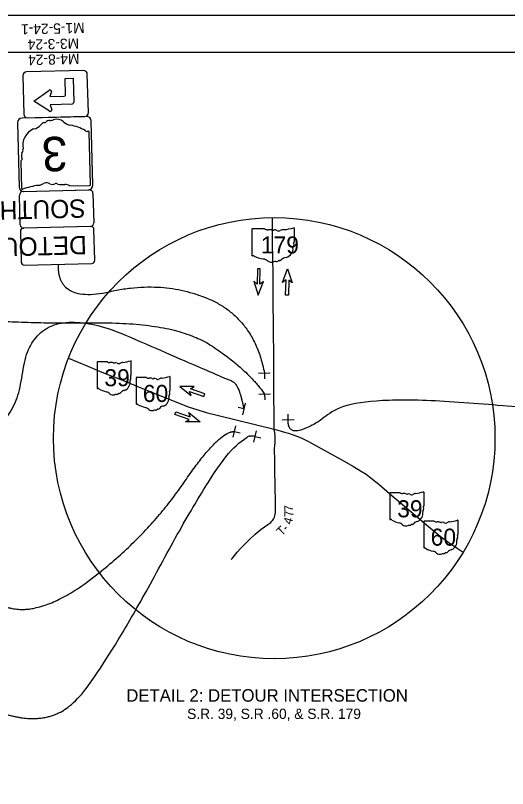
# Model space of a CAD drawing. Extents: x -15.3 to 34, y 0 to 22.
# Drawn here: x 20.86 to 27.55, y 11.48 to 22 of the extents above; entities that cross this region are included whole.
import ezdxf

# ---------------------------------------------------------------- set-up
doc = ezdxf.new("R2010")
doc.units = 0
for name, color, linetype in [('GM_X_State_Route', 7, 'Continuous'), ('GM_X_State_Shield', 7, 'Continuous'), ('GM_X_Township_Road', 7, 'Continuous'), ('GM_X_Township_Road_Text', 7, 'Continuous'), ('PM_P_Cells', 7, 'Continuous'), ('SC_Scratch1', 7, 'Continuous'), ('SH_Border', 7, 'Continuous'), ('SH_Cut_Line', 7, 'Continuous'), ('SH_Text', 7, 'Continuous'), ('SN_P_Signs', 7, 'Continuous')]:
    doc.layers.add(name, color=color, linetype=linetype)

msp = doc.modelspace()

# ---------------------------------------------------------------- linework, layer by layer
at = {"layer": 'GM_X_State_Route'}
for points in [[(21.578, 17.336), (21.841, 17.229), (22.002, 17.163), (22.124, 17.113), (22.266, 17.055), (22.388, 17.007), (22.509, 16.958), (22.651, 16.9), (23.116, 16.711), (23.218, 16.673), (23.322, 16.638), (23.448, 16.601), (23.617, 16.558), (24.374, 16.374), (24.372, 16.621), (24.368, 16.774), (24.369, 16.905), (24.369, 17.058), (24.368, 17.211), (24.369, 17.386), (24.365, 17.692), (24.364, 17.844), (24.362, 18.041), (24.36, 18.326), (24.359, 18.457), (24.356, 18.719), (24.353, 18.871), (24.351, 19.046), (24.351, 19.199), (24.351, 19.25)], [(24.374, 16.374), (24.409, 16.363), (24.47, 16.346), (24.515, 16.333), (24.567, 16.318), (24.62, 16.3), (24.682, 16.278), (24.743, 16.252), (24.841, 16.203), (25.015, 16.11), (25.283, 15.961), (25.454, 15.863), (25.549, 15.807), (25.623, 15.759), (25.693, 15.707), (25.795, 15.623), (25.978, 15.467), (26.145, 15.325), (26.445, 15.07), (26.632, 14.918), (26.736, 14.839), (26.861, 14.751), (26.942, 14.697)]]:
    msp.add_lwpolyline(points, dxfattribs=at)
at = {"layer": 'GM_X_State_Shield'}
for p, q in [((24.069, 19.09), (24.069, 18.737)), ((24.245, 19.096), (24.075, 19.096)), ((24.649, 18.92), (24.649, 19.104)), ((24.649, 18.92), (24.649, 18.92)), ((21.968, 17.283), (21.968, 16.931)), ((22.108, 17.289), (21.972, 17.289)), ((22.432, 17.114), (22.432, 17.298)), ((22.432, 17.114), (22.432, 17.114)), ((22.497, 17.07), (22.497, 16.717)), ((22.637, 17.076), (22.501, 17.076)), ((22.961, 16.9), (22.961, 17.084)), ((22.961, 16.9), (22.961, 16.9)), ((25.947, 15.5), (25.947, 15.148)), ((26.087, 15.506), (25.951, 15.506)), ((26.411, 15.331), (26.411, 15.515)), ((26.411, 15.331), (26.411, 15.331)), ((26.409, 15.114), (26.409, 14.762)), ((26.549, 15.12), (26.413, 15.12)), ((26.873, 14.945), (26.873, 15.129)), ((26.873, 14.945), (26.873, 14.945))]:
    msp.add_line(p, q, dxfattribs=at)
for centre, radius, start, end in [((21.973, 17.284), 0.00538, 98.1301, 188.1301), ((22.141, 17.33), 0.0521, 231.6195, 271.1119), ((22.158, 17.092), 0.187, 80.4867, 94.9883), ((22.2, 17.286), 0.015, 219.7921, 297.1024), ((22.222, 17.245), 0.0313, 54.4667, 119.1411), ((22.263, 17.301), 0.0376, 233.8562, 294.8282), ((22.329, 17.182), 0.099, 97.3462, 120.7689), ((22.267, 17.769), 0.492, 275.8445, 288.9065), ((22.427, 17.299), 0.00517, 351.8621, 97.738), ((22.45, 17.037), 0.0349, 136.8065, 186.9296), ((22.431, 17.1), 0.00799, 107.944, 210.337), ((22.38, 17.077), 0.048, 340.033, 23.6496), ((22.426, 17.113), 0.00553, 289.6038, 7.7341), ((22.502, 17.07), 0.00538, 98.1301, 188.1301), ((22.669, 17.117), 0.0521, 231.6195, 271.1119), ((22.687, 16.878), 0.187, 80.4867, 94.9883), ((22.729, 17.072), 0.015, 219.7921, 297.1024), ((22.751, 17.032), 0.0313, 54.4667, 119.1411), ((22.792, 17.087), 0.0376, 233.8562, 294.8282), ((22.858, 16.968), 0.099, 97.3462, 120.7689), ((22.795, 17.556), 0.492, 275.8445, 288.9065), ((22.955, 17.085), 0.00517, 351.8621, 97.738), ((22.294, 17.013), 0.123, 292.3089, 8.9858), ((21.973, 16.93), 0.00542, 171.9584, 258.3066), ((21.974, 16.966), 0.0414, 267.339, 280.6039), ((21.982, 16.911), 0.0149, 29.7484, 93.2717), ((22.171, 17.227), 0.355, 240.4129, 257.1985), ((22.065, 16.773), 0.111, 47.1842, 75.836), ((22.185, 16.909), 0.0706, 230.7004, 286.2918), ((22.226, 16.787), 0.058, 85.6951, 111.2099), ((22.231, 16.883), 0.0376, 268.777, 315.5493), ((22.265, 16.848), 0.0106, 65.7517, 132.6484), ((22.261, 16.897), 0.0398, 282.8732, 323.2771), ((22.346, 16.832), 0.0674, 94.4031, 142.5768), ((22.979, 16.823), 0.0349, 136.8065, 186.9296), ((22.959, 16.887), 0.00799, 107.944, 210.337), ((22.909, 16.863), 0.048, 340.033, 23.6496), ((22.955, 16.899), 0.00553, 289.6038, 7.7341), ((22.823, 16.8), 0.123, 292.3089, 8.9858), ((22.502, 16.717), 0.00542, 171.9584, 258.3066), ((22.503, 16.753), 0.0414, 267.339, 280.6039), ((22.511, 16.697), 0.0149, 29.7484, 93.2717), ((22.7, 17.014), 0.355, 240.4129, 257.1985), ((22.594, 16.559), 0.111, 47.1842, 75.836), ((22.714, 16.695), 0.0706, 230.7004, 286.2918), ((22.755, 16.574), 0.058, 85.6951, 111.2099), ((22.76, 16.669), 0.0376, 268.777, 315.5493), ((22.794, 16.635), 0.0106, 65.7517, 132.6484), ((22.789, 16.683), 0.0398, 282.8732, 323.2771), ((22.875, 16.619), 0.0674, 94.4031, 142.5768), ((25.952, 15.501), 0.00538, 98.1301, 188.1301), ((26.119, 15.547), 0.0521, 231.6195, 271.1119), ((26.137, 15.309), 0.187, 80.4867, 94.9883), ((26.179, 15.503), 0.015, 219.7921, 297.1024), ((26.201, 15.462), 0.0313, 54.4667, 119.1411), ((26.242, 15.518), 0.0376, 233.8562, 294.8282), ((26.308, 15.399), 0.099, 97.3462, 120.7689), ((26.245, 15.987), 0.492, 275.8445, 288.9065), ((26.405, 15.516), 0.00517, 351.8621, 97.738), ((26.273, 15.23), 0.123, 292.3089, 8.9858), ((26.429, 15.254), 0.0349, 136.8065, 186.9296), ((26.409, 15.317), 0.00799, 107.944, 210.337), ((26.359, 15.294), 0.048, 340.033, 23.6496), ((26.405, 15.33), 0.00553, 289.6038, 7.7341), ((25.952, 15.147), 0.00542, 171.9584, 258.3066), ((25.953, 15.183), 0.0414, 267.339, 280.6039), ((25.961, 15.128), 0.0149, 29.7484, 93.2717), ((26.15, 15.444), 0.355, 240.4129, 257.1985), ((26.044, 14.99), 0.111, 47.1842, 75.836), ((26.164, 15.126), 0.0706, 230.7004, 286.2918), ((26.205, 15.004), 0.058, 85.6951, 111.2099), ((26.21, 15.1), 0.0376, 268.777, 315.5493), ((26.244, 15.066), 0.0106, 65.7517, 132.6484), ((26.239, 15.114), 0.0398, 282.8732, 323.2771), ((26.325, 15.049), 0.0674, 94.4031, 142.5768), ((26.414, 15.115), 0.00538, 98.1301, 188.1301), ((26.582, 15.161), 0.0521, 231.6195, 271.1119), ((26.599, 14.923), 0.187, 80.4867, 94.9883), ((26.641, 15.117), 0.015, 219.7921, 297.1024), ((26.664, 15.076), 0.0313, 54.4667, 119.1411), ((26.704, 15.132), 0.0376, 233.8562, 294.8282), ((26.77, 15.013), 0.099, 97.3462, 120.7689), ((26.708, 15.601), 0.492, 275.8445, 288.9065), ((26.868, 15.13), 0.00517, 351.8621, 97.738), ((26.872, 14.931), 0.00799, 107.944, 210.337), ((26.867, 14.944), 0.00553, 289.6038, 7.7341), ((26.735, 14.844), 0.123, 292.3089, 8.9858), ((26.891, 14.868), 0.0349, 136.8065, 186.9296), ((26.821, 14.908), 0.048, 340.033, 23.6496), ((26.414, 14.761), 0.00542, 171.9584, 258.3066), ((26.415, 14.797), 0.0414, 267.339, 280.6039), ((26.423, 14.742), 0.0149, 29.7484, 93.2717), ((26.612, 15.058), 0.355, 240.4129, 257.1985), ((26.787, 14.663), 0.0674, 94.4031, 142.5768), ((26.506, 14.604), 0.111, 47.1842, 75.836), ((26.626, 14.74), 0.0706, 230.7004, 286.2918), ((26.667, 14.618), 0.058, 85.6951, 111.2099), ((26.672, 14.714), 0.0376, 268.777, 315.5493), ((26.706, 14.68), 0.0106, 65.7517, 132.6484), ((26.702, 14.728), 0.0398, 282.8732, 323.2771)]:
    msp.add_arc(centre, radius, start, end, dxfattribs=at)
for centre, major_axis, start_param, end_param in [((24.076, 19.09), (0.00672, 0), 1.712693, 3.28349), ((24.285, 19.137), (0.0652, 0), 4.042523, 4.731795), ((24.307, 18.898), (0.234, 0), 1.404758, 1.657858), ((24.36, 19.092), (0.0188, 0), 3.836095, 5.185415), ((24.388, 19.051), (0.0391, 0), 0.950623, 2.079405), ((24.438, 19.107), (0.047, 0), 4.081561, 5.145723), ((24.521, 18.988), (0.124, 0), 1.699011, 2.107814), ((24.443, 19.576), (0.615, 0), 4.814394, 5.042369), ((24.643, 19.105), (0.00646, 0), 6.141152, 7.989035), ((24.477, 18.82), (0.154, 0), 5.101752, 6.440018), ((24.672, 18.843), (0.0436, 0), 2.387724, 3.262537), ((24.648, 18.907), (0.00999, 0), 1.883978, 3.671073), ((24.584, 18.883), (0.06, 0), 5.934695, 6.695948), ((24.642, 18.919), (0.00691, 0), 5.05454, 6.418171), ((24.076, 18.737), (0.00678, 0), 3.00124, 4.508301), ((24.077, 18.773), (0.0517, 0), 4.665946, 4.897461), ((24.088, 18.717), (0.0187, 0), 0.519207, 1.627899), ((24.323, 19.034), (0.444, 0), 4.195997, 4.488961), ((24.191, 18.579), (0.139, 0), 0.823519, 1.323587), ((24.341, 18.715), (0.0882, 0), 4.026481, 4.996735), ((24.392, 18.594), (0.0725, 0), 1.495662, 1.94098), ((24.398, 18.689), (0.047, 0), 4.691044, 5.507374), ((24.441, 18.655), (0.0132, 0), 1.147584, 2.315152), ((24.435, 18.703), (0.0497, 0), 4.937069, 5.64225), ((24.542, 18.639), (0.0843, 0), 1.647645, 2.488434)]:
    msp.add_ellipse(centre, major_axis=major_axis, ratio=0.8, start_param=start_param, end_param=end_param, dxfattribs=at)
at = {"layer": 'GM_X_Township_Road'}
msp.add_lwpolyline([(23.79, 14.598), (23.805, 14.614), (23.872, 14.699), (23.915, 14.748), (23.96, 14.796), (24.039, 14.871), (24.116, 14.945), (24.199, 15.013), (24.29, 15.076), (24.327, 15.104), (24.342, 15.119), (24.356, 15.136), (24.368, 15.155), (24.377, 15.174), (24.385, 15.194), (24.389, 15.216), (24.392, 15.237), (24.393, 15.281), (24.391, 15.39), (24.388, 15.587), (24.384, 15.826), (24.382, 15.979), (24.38, 16.067), (24.38, 16.107), (24.385, 16.147), (24.389, 16.197), (24.387, 16.276), (24.381, 16.326), (24.374, 16.367), (24.374, 16.374)], dxfattribs=at)
at = {"layer": 'PM_P_Cells'}
for p, q in [((24.147, 18.552), (24.142, 18.346)), ((24.185, 18.551), (24.147, 18.552)), ((24.166, 18.552), (24.166, 18.552)), ((24.18, 18.345), (24.185, 18.551)), ((24.488, 18.366), (24.557, 18.552)), ((24.557, 18.552), (24.557, 18.552)), ((24.557, 18.552), (24.618, 18.363)), ((24.142, 18.346), (24.097, 18.385)), ((24.097, 18.385), (24.157, 18.195)), ((24.157, 18.195), (24.227, 18.381)), ((24.227, 18.381), (24.18, 18.345)), ((24.535, 18.402), (24.488, 18.366)), ((24.53, 18.196), (24.535, 18.402)), ((24.572, 18.401), (24.567, 18.195)), ((24.618, 18.363), (24.572, 18.401)), ((24.157, 18.195), (24.157, 18.195)), ((24.567, 18.195), (24.53, 18.196)), ((24.548, 18.196), (24.548, 18.196)), ((23.09, 16.953), (23.09, 16.953)), ((23.09, 16.953), (23.245, 16.829)), ((23.289, 16.952), (23.09, 16.953)), ((23.238, 16.921), (23.289, 16.952)), ((23.245, 16.829), (23.225, 16.885)), ((23.225, 16.885), (23.42, 16.817)), ((23.432, 16.852), (23.238, 16.921)), ((23.42, 16.817), (23.432, 16.852)), ((23.426, 16.835), (23.426, 16.835)), ((23.026, 16.573), (23.039, 16.609)), ((23.221, 16.505), (23.026, 16.573)), ((23.032, 16.591), (23.032, 16.591)), ((23.039, 16.609), (23.233, 16.54)), ((23.233, 16.54), (23.213, 16.597)), ((23.213, 16.597), (23.368, 16.473)), ((23.17, 16.474), (23.221, 16.505)), ((23.368, 16.473), (23.17, 16.474)), ((23.368, 16.473), (23.368, 16.473))]:
    msp.add_line(p, q, dxfattribs=at)
at = {"layer": 'SH_Border'}
msp.add_lwpolyline([(1.5, 21.5), (33.5, 21.5), (33.5, 0.5), (1.5, 0.5)], close=True, dxfattribs=at)
at = {"layer": 'SH_Cut_Line'}
msp.add_lwpolyline([(0, 0), (34, 0), (34, 22), (0, 22)], close=True, dxfattribs=at)
at = {"layer": 'SH_Text'}
msp.add_circle((24.375, 16.25), 3, dxfattribs=at)
for points in [[(21.437, 18.617), (21.425, 18.079), (22.86, 18.408), (24.096, 17.885), (24.242, 17.138)], [(19.655, 18.426), (19.572, 17.947), (20.883, 17.807), (23.028, 17.829), (24.003, 17.194), (24.244, 16.85)], [(19.821, 16.303), (20.813, 16.063), (21.093, 18.199), (23.713, 17.06), (23.897, 16.988), (23.961, 16.647)], [(29.021, 17.807), (29.026, 16.783), (28.756, 16.582), (25.512, 16.854), (24.827, 16.364), (24.556, 16.333), (24.565, 16.497)], [(20.729, 13.956), (21.193, 13.792), (22.671, 14.944), (23.628, 16.352), (23.835, 16.339)], [(20.684, 12.508), (21.281, 12.313), (22, 12.975), (23.853, 16.417), (24.116, 16.271)]]:
    msp.add_open_spline(points, degree=2, dxfattribs=at)
at = {"layer": 'SN_P_Signs'}
for p, q in [((21.784, 21.251), (21.009, 21.231)), ((20.96, 21.18), (20.974, 20.655)), ((21.532, 21.143), (21.641, 21.146)), ((21.538, 20.917), (21.532, 21.143)), ((21.641, 21.146), (21.65, 20.818)), ((21.849, 20.678), (21.835, 21.203)), ((21.11, 20.835), (21.31, 20.98)), ((21.346, 20.967), (21.327, 20.896)), ((21.317, 20.701), (21.11, 20.835)), ((21.327, 20.896), (21.522, 20.901)), ((21.627, 20.794), (21.33, 20.786)), ((21.33, 20.786), (21.353, 20.717)), ((21.627, 20.794), (21.627, 20.794)), ((21.025, 20.607), (21.8, 20.627)), ((21.879, 19.7), (21.86, 20.412)), ((20.933, 20.018), (20.942, 19.646)), ((20.933, 20.018), (20.933, 20.018)), ((21.595, 19.681), (21.87, 19.688)), ((20.961, 19.605), (21.861, 19.628)), ((21.912, 19.579), (21.923, 19.179)), ((20.923, 19.153), (20.913, 19.553)), ((21.874, 19.128), (20.974, 19.105)), ((24.162, 17.136), (24.322, 17.14)), ((24.242, 17.138), (24.244, 17.058)), ((24.164, 16.848), (24.324, 16.852)), ((24.244, 16.85), (24.246, 16.77)), ((23.98, 16.725), (23.942, 16.569)), ((23.961, 16.647), (23.883, 16.666)), ((24.565, 16.497), (24.564, 16.577)), ((23.818, 16.261), (23.853, 16.417)), ((24.645, 16.499), (24.485, 16.496)), ((23.835, 16.339), (23.913, 16.322)), ((24.098, 16.193), (24.133, 16.349)), ((24.116, 16.271), (24.194, 16.254))]:
    msp.add_line(p, q, dxfattribs=at)
for points in [[(21.823, 20.627), (20.948, 20.605)], [(20.887, 20.541), (20.91, 19.666)], [(21.909, 19.692), (21.887, 20.566)], [(20.974, 19.605), (21.848, 19.627)], [(20.925, 19.064), (20.936, 18.644)], [(21.884, 19.128), (20.964, 19.105)], [(21.936, 18.669), (21.925, 19.089)], [(20.977, 18.605), (21.897, 18.628)]]:
    msp.add_lwpolyline(points, dxfattribs=at)
for centre, radius, start, end in [((21.785, 21.201), 0.05, 1.4753, 91.4753), ((21.01, 21.181), 0.05, 91.4753, 181.4753), ((21.325, 20.966), 0.0209, 1.4736, 136.4752), ((21.522, 20.916), 0.0156, 271.4753, 1.4753), ((21.626, 20.818), 0.0234, 271.4753, 1.4753), ((21.024, 20.657), 0.05, 181.4753, 271.4753), ((21.332, 20.716), 0.0209, 226.4754, 1.4736), ((21.799, 20.677), 0.05, 271.4753, 1.4753), ((21.824, 20.565), 0.0625, 1.4753, 91.4753), ((20.95, 20.542), 0.0625, 91.4753, 181.4753), ((21.091, 20.592), 0.136, 275.8784, 324.052), ((21.267, 20.465), 0.0803, 104.3485, 144.7524), ((21.256, 20.563), 0.0214, 247.227, 314.1237), ((21.326, 20.496), 0.0759, 90.2523, 137.0246), ((21.331, 20.689), 0.117, 267.1704, 292.6852), ((21.42, 20.445), 0.143, 52.1757, 107.7671), ((21.656, 20.726), 0.225, 228.6595, 257.3113), ((21.206, 20.229), 0.249, 113.7842, 190.4611), ((21.466, 19.803), 0.718, 61.8882, 78.6738), ((21.83, 20.452), 0.0302, 211.2237, 274.747), ((21.85, 20.34), 0.0836, 88.8143, 102.0792), ((21.849, 20.413), 0.011, 353.4337, 79.7819), ((21.036, 20.095), 0.097, 161.5083, 205.1249), ((20.891, 20.173), 0.0705, 318.2818, 8.4049), ((20.944, 20.02), 0.0112, 111.0791, 189.2094), ((20.934, 20.046), 0.0162, 289.4193, 31.8123), ((21.301, 18.703), 0.994, 97.3198, 110.3818), ((21.143, 19.887), 0.2, 278.8215, 302.2442), ((21.284, 19.649), 0.076, 55.3315, 116.3035), ((21.362, 19.764), 0.0632, 235.942, 300.6164), ((21.409, 19.683), 0.0304, 41.2674, 118.5777), ((21.485, 20.078), 0.378, 261.962, 276.4636), ((21.532, 19.597), 0.105, 53.0948, 92.5872), ((21.847, 19.69), 0.0625, 271.4753, 1.4753), ((21.868, 19.699), 0.0109, 279.6054, 9.6054), ((20.972, 19.667), 0.0625, 181.4753, 271.4753), ((20.963, 19.555), 0.05, 91.4753, 181.4753), ((20.953, 19.645), 0.0104, 173.3374, 279.2133), ((21.862, 19.578), 0.05, 1.4753, 91.4753), ((20.973, 19.155), 0.05, 181.4753, 271.4753), ((21.873, 19.178), 0.05, 271.4753, 1.4753), ((20.965, 19.065), 0.04, 91.4753, 181.4753), ((21.885, 19.088), 0.04, 1.4753, 91.4753), ((20.976, 18.645), 0.04, 181.4753, 271.4753), ((21.896, 18.668), 0.04, 271.4753, 1.4753)]:
    msp.add_arc(centre, radius, start, end, dxfattribs=at)

# ---------------------------------------------------------------- texts
at = {"layer": 'GM_X_State_Shield'}
for s, p in [('179', (24.193, 18.762)), ('39', (22.067, 16.956)), ('60', (22.589, 16.742)), ('39', (26.046, 15.173)), ('60', (26.501, 14.787))]:
    msp.add_text(s, height=0.232, dxfattribs=at).set_placement(p)
at = {"layer": 'GM_X_Township_Road_Text'}
for s, rotation, p in [('7', 90.4007, (24.632, 15.251)), ('7', 91.9707, (24.634, 15.178)), ('4', 74.5448, (24.61, 15.067)), ('T', 44.0363, (24.476, 14.91)), ('-', 46.611, (24.545, 14.976))]:
    msp.add_text(s, height=0.12, rotation=rotation, dxfattribs=at).set_placement(p)
at = {"layer": 'SC_Scratch1'}
for s, p in [('M1-5-24-1', (21.796, 21.902)), ('M3-3-24', (21.721, 21.69)), ('M4-8-24', (21.726, 21.48))]:
    msp.add_text(s, height=0.14, rotation=181.4753, dxfattribs=at).set_placement(p)
at = {"layer": 'SH_Text'}
for s, height, p in [('DETAIL 2: DETOUR INTERSECTION', 0.17, (22.364, 12.665)), ('S.R. 39, S.R .60, & S.R. 179', 0.14, (23.191, 12.43))]:
    msp.add_text(s, height=height, dxfattribs=at).set_placement(p)
at = {"layer": 'SN_P_Signs'}
for s, height, p in [('3', 0.469, (21.559, 20.354)), ('SOUTH', 0.25, (21.81, 19.501)), ('DETOUR', 0.25, (21.825, 19.002))]:
    msp.add_text(s, height=height, rotation=181.4753, dxfattribs=at).set_placement(p)

doc.saveas('drawing.dxf')
